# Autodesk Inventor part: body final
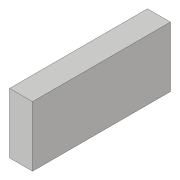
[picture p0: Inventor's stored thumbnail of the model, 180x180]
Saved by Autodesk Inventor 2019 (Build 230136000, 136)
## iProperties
Created: 2020-02
Part Number: body final
Material: Generic
Document SubType Name: Modeling
Designer: Krupashree
Density: 1 g/cm^3
Appearance: Default
Author: Krupashree
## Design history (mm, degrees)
sketch "Sketch1"
  geometry: L1 (13.075, 37.216)-(13.075, -52.784); L2 (13.075, -52.784)-(-26.246, -52.784); L3 (-26.246, -52.784)-(-26.246, -36.781); L4 (-26.246, -36.781)-(-1.402, -36.781); L5 (-1.402, -36.781)-(-1.402, 24.586); L6 (-1.402, 24.586)-(-26.246, 24.586); L7 (-26.246, 24.586)-(-26.246, 37.216); L8 (-26.246, 37.216)-(13.075, 37.216); 1 further point
  constraints: 16 end point, 2 point on line, 1 perpendicular, 1 vertical
  dimensions: "d1" = 90 distance of L1.start L1.end
extrude "Extrusion1" new body sketch "Sketch1" distance "d2" = 10; taper "d3" = 0 deg
sketch "Sketch2"
  geometry: C1 r 0.25 at (-45.597, -11.134); C2 r 0.25 at (-4.949, 7.953); C3 r 0.25 at (30.044, -11.134); 1 further point
  constraints: 3 centre point
  dimensions: "d4" = 0.5 diameter of C1; "d5" = 0.5 diameter of C2; "d6" = 0.5 diameter of C3
extrude "Extrusion2" cut sketch "Sketch2" extent not by distance; stored distance "d7" = 10; taper "d8" = 0 deg
sketch "Sketch3"
  geometry: C1 r 0.25 at (31.08, -10.36); 1 further point
  constraints: 1 centre point
  dimensions: "d9" = 0.5 diameter of C1
extrude "Extrusion3" cut sketch "Sketch3" extent not by distance; stored distance "d10" = 0; taper "d11" = 0 deg
sketch "Sketch4"
  geometry: L1 (-37.216, -26.246)-(-24.586, -26.246) reference; L2 (52.784, 13.075)-(-37.216, 13.075) reference; L3 (-37.216, -26.246)-(52.784, -26.246); L4 (52.784, -26.246)-(52.784, 13.075); L5 (52.784, 13.075)-(-37.216, 13.075); L6 (-37.216, 13.075)-(-37.216, -26.246); 1 further point
  constraints: 8 end point, 2 parallel, 1 horizontal, 1 perpendicular
extrude "Extrusion4" join sketch "Sketch4" distance "d12" = 5; taper "d13" = 0 deg
sketch "Sketch5"
  geometry: L1 (-18.693, -13.062)-(6.982, -13.062); L2 (6.982, -13.062)-(6.982, -21.058); L3 (6.982, -21.058)-(-18.693, -21.058); L4 (-18.693, -21.058)-(-18.693, -13.062); 1 further point
  constraints: 8 end point, 2 parallel, 1 horizontal, 1 perpendicular
extrude "Extrusion5" join sketch "Sketch5" distance "d14" = 2; taper "d15" = 0 deg
body "Solid1"
